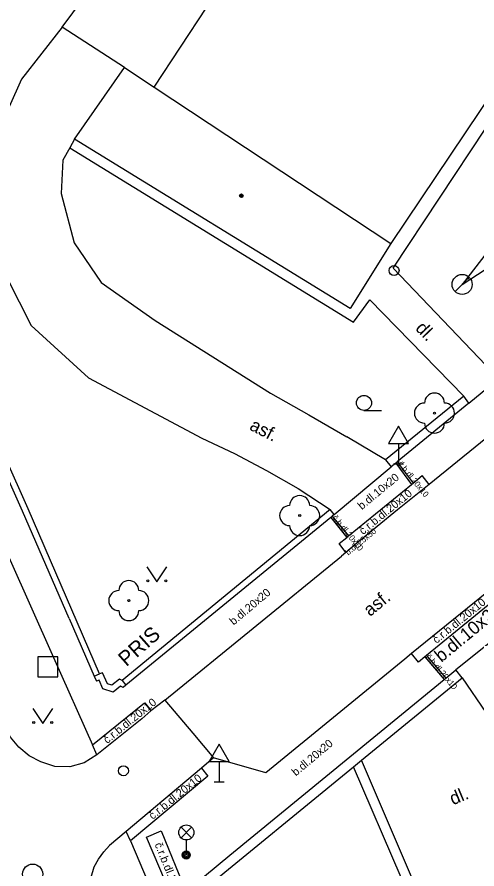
# Model space of a CAD drawing. Extents: x -600391 to -599491, y -1160176 to -1159402.
# Drawn here: x -599970.71 to -599947.75, y -1159959.22 to -1159916.65 of the extents above; entities that cross this region are included whole.
import ezdxf

# ---------------------------------------------------------------- set-up
doc = ezdxf.new("R2010")
doc.units = 0
for name, color, linetype in [('Level 10', 7, 'Continuous'), ('Level 11', 7, 'Continuous'), ('Level 14', 7, 'Continuous'), ('Level 15', 7, 'Continuous'), ('Level 22', 7, 'Continuous'), ('Level 26', 7, 'Continuous'), ('Level 27', 7, 'Continuous'), ('Level 28', 7, 'Continuous'), ('Level 31', 7, 'Continuous'), ('Level 33', 7, 'Continuous'), ('Level 34', 7, 'Continuous'), ('Level 36', 7, 'Continuous'), ('Level 39', 7, 'Continuous'), ('Level 40', 7, 'Continuous'), ('Level 41', 7, 'Continuous'), ('Level 5', 7, 'Continuous'), ('Level 7', 7, 'Continuous'), ('Level 8', 7, 'Continuous')]:
    doc.layers.add(name, color=color, linetype=linetype)

msp = doc.modelspace()

# ---------------------------------------------------------------- linework, layer by layer
at = {"layer": 'Level 10'}
for points in [[(-599911.82, -1159908.6), (-599914.96, -1159911.33), (-599925.54, -1159919.92), (-599941.57, -1159933.04), (-599950.13, -1159940)], [(-599907.98, -1159913.43), (-599912.46, -1159917.06), (-599914.77, -1159918.94), (-599915.47, -1159919.52), (-599917.71, -1159921.29), (-599918.18, -1159921.69), (-599922.35, -1159925.05), (-599925.54, -1159927.69), (-599925.9, -1159927.97), (-599936.86, -1159936.91), (-599937.36, -1159937.36), (-599940.49, -1159939.85), (-599940.86, -1159940.15), (-599941.25, -1159940.48), (-599946.99, -1159945.18), (-599947.87, -1159945.9)], [(-599950.13, -1159940), (-599951.71, -1159941.28), (-599953.75, -1159942.94)], [(-599953.75, -1159942.94), (-599954.29, -1159943.4), (-599954.52, -1159943.59)], [(-599963.33, -1159950.78), (-599954.52, -1159943.59)], [(-599947.87, -1159945.9), (-599951.01, -1159948.46)], [(-599951.35, -1159948.74), (-599958.29, -1159954.41)], [(-599951.01, -1159948.46), (-599951.35, -1159948.74)], [(-599963.33, -1159950.78), (-599964.03, -1159951.32), (-599964.48, -1159951.71)], [(-599964.48, -1159951.71), (-599966.73, -1159953.52)], [(-599969.53, -1159953.86), (-599970.11, -1159953.56), (-599970.62, -1159953.14), (-599971.04, -1159952.63), (-599971.35, -1159952.05)], [(-599966.73, -1159953.52), (-599967.36, -1159953.92), (-599968.08, -1159954.11), (-599968.82, -1159954.09), (-599969.53, -1159953.86)], [(-599958.29, -1159954.41), (-599960.91, -1159953.67), (-599961.5, -1159954.18), (-599965.26, -1159957.34), (-599966.09, -1159958.04)], [(-599966.86, -1159959.11), (-599966.64, -1159958.73), (-599966.38, -1159958.37), (-599966.09, -1159958.04)], [(-599966.74, -1159962.81), (-599967.06, -1159961.92), (-599967.19, -1159960.97), (-599967.13, -1159960.02), (-599966.86, -1159959.11)]]:
    msp.add_lwpolyline(points, dxfattribs=at)
at = {"layer": 'Level 11'}
for points in [[(-600002.37, -1159877.7), (-599997.64, -1159887.06), (-599995.54, -1159891.34), (-599992.33, -1159897.82), (-599988.83, -1159905.02), (-599982.55, -1159918.34), (-599977.69, -1159928.9), (-599968.89, -1159948.65)], [(-599965.34, -1159919.17), (-599968.46, -1159917.15), (-599964.35, -1159911.61), (-599976.85, -1159896), (-599973.76, -1159893.33)], [(-599951.94, -1159929.2), (-599940.37, -1159911.69)], [(-599968.46, -1159917.15), (-599970.48, -1159919.75), (-599971.67, -1159922.37), (-599972.15, -1159925.31), (-599971.83, -1159928.48), (-599970, -1159932.06), (-599967.15, -1159934.67), (-599961.48, -1159937.69)], [(-599967.84, -1159922.75), (-599968.08, -1159923.18), (-599968.42, -1159923.8), (-599968.5, -1159925.47), (-599967.86, -1159927.93), (-599966.51, -1159929.91), (-599963.81, -1159931.82), (-599958.06, -1159935.45)], [(-599968.08, -1159923.18), (-599953.91, -1159931.89)], [(-599951.94, -1159929.2), (-599946.95, -1159934.41)], [(-599953.91, -1159931.89), (-599953.1, -1159930.78)], [(-599953.1, -1159930.78), (-599948.41, -1159935.6)], [(-599958.06, -1159935.45), (-599956.14, -1159936.53), (-599954.24, -1159937.62)], [(-599961.48, -1159937.69), (-599959.85, -1159938.46), (-599958.25, -1159939.3), (-599956.68, -1159940.2), (-599955.08, -1159941.26)], [(-599952.31, -1159938.78), (-599954.24, -1159937.62)], [(-599951.8, -1159938.94), (-599951.02, -1159940)], [(-599951.73, -1159938.88), (-599950.94, -1159939.94)], [(-599954.29, -1159943.4), (-599954.63, -1159942.96), (-599954.25, -1159942.65), (-599954.17, -1159942.58), (-599951.02, -1159940), (-599950.94, -1159939.94), (-599950.49, -1159939.56)], [(-599950.13, -1159940), (-599950.49, -1159939.56)], [(-599955.05, -1159941.66), (-599954.25, -1159942.65)], [(-599954.97, -1159941.59), (-599954.17, -1159942.58)], [(-599946.99, -1159945.18), (-599946.66, -1159945.62), (-599947.11, -1159945.98), (-599947.19, -1159946.04), (-599950.27, -1159948.55), (-599950.35, -1159948.61), (-599950.67, -1159948.88), (-599951.01, -1159948.46)], [(-599968.89, -1159948.65), (-599966.94, -1159953.01)], [(-599950.35, -1159948.61), (-599949.38, -1159949.75)], [(-599950.27, -1159948.55), (-599949.3, -1159949.68)], [(-599948.48, -1159949.66), (-599943.76, -1159956.6)], [(-599966.94, -1159953.01), (-599964.35, -1159950.91), (-599964.03, -1159951.32)], [(-599963.33, -1159950.78), (-599961.94, -1159952.43), (-599960.91, -1159953.67)], [(-599966.73, -1159953.52), (-599966.94, -1159953.01)], [(-599950.96, -1159959.73), (-599953.51, -1159953.78)], [(-599961.5, -1159954.18), (-599961.19, -1159954.58), (-599965.04, -1159957.82)], [(-599951.53, -1159959.65), (-599953.91, -1159954.11)], [(-599962.27, -1159960.38), (-599962.96, -1159960.65), (-599964.24, -1159957.63), (-599963.52, -1159957.31), (-599962.27, -1159960.38)], [(-599965.04, -1159957.82), (-599965.26, -1159957.34)], [(-599965.04, -1159957.82), (-599962.63, -1159963.51)]]:
    msp.add_lwpolyline(points, dxfattribs=at)
at = {"layer": 'Level 14'}
for points in [[(-599941.8, -1159921.35), (-599948.49, -1159930.01)], [(-599948.49, -1159930.01), (-599940.79, -1159924.98)]]:
    msp.add_lwpolyline(points, dxfattribs=at)
at = {"layer": 'Level 15'}
msp.add_lwpolyline([(-599948.24, -1159929.69), (-599948.18, -1159929.73)], dxfattribs=at)
at = {"layer": 'Level 22'}
for centre in [(-599949.87, -1159936.44), (-599956.6, -1159941.56), (-599965.13, -1159945.81)]:
    msp.add_circle(centre, 0.05, dxfattribs=at)
for centre, start, end in [((-599949.87, -1159935.94), 0, 180), ((-599950.37, -1159936.44), 90, 270), ((-599949.37, -1159936.44), 270, 90), ((-599949.87, -1159936.94), 180, 0), ((-599956.6, -1159941.06), 0, 180), ((-599957.1, -1159941.56), 90, 270), ((-599956.1, -1159941.56), 270, 90), ((-599956.6, -1159942.06), 180, 0), ((-599965.13, -1159945.31), 0, 180), ((-599965.63, -1159945.81), 90, 270), ((-599964.63, -1159945.81), 270, 90), ((-599965.13, -1159946.31), 180, 0)]:
    msp.add_arc(centre, 0.5, start, end, dxfattribs=at)
at = {"layer": 'Level 26'}
msp.add_lwpolyline([(-599969.67, -1159949.62), (-599968.67, -1159949.62), (-599968.67, -1159948.62), (-599969.67, -1159948.62)], close=True, dxfattribs=at)
at = {"layer": 'Level 27'}
msp.add_line((-599948.844, -1159930.363), (-599948.137, -1159929.656), dxfattribs=at)
for centre in [(-599948.49, -1159930.01), (-599969.93, -1159959.47)]:
    msp.add_circle(centre, 0.5, dxfattribs=at)
at = {"layer": 'Level 28'}
msp.add_circle((-599951.89, -1159929.32), 0.25, dxfattribs=at)
at = {"layer": 'Level 31'}
msp.add_circle((-599965.4, -1159954.31), 0.25, dxfattribs=at)
at = {"layer": 'Level 33'}
for p, q in [((-599962.525, -1159957.66), (-599961.995, -1159957.13)), ((-599962.525, -1159957.13), (-599961.995, -1159957.66)), ((-599962.26, -1159957.77), (-599962.26, -1159958.52))]:
    msp.add_line(p, q, dxfattribs=at)
for centre, radius in [((-599962.26, -1159957.395), 0.375), ((-599962.26, -1159958.52), 0.2), ((-599962.26, -1159958.52), 0.145), ((-599962.26, -1159958.52), 0.0876)]:
    msp.add_circle(centre, radius, dxfattribs=at)
at = {"layer": 'Level 34'}
for p, q in [((-599951.66, -1159937.952), (-599951.66, -1159938.97)), ((-599951.91, -1159938.97), (-599951.41, -1159938.97)), ((-599960.62, -1159953.842), (-599960.62, -1159954.86)), ((-599960.87, -1159954.86), (-599960.37, -1159954.86))]:
    msp.add_line(p, q, dxfattribs=at)
for points in [[(-599952.16, -1159937.952), (-599951.16, -1159937.952), (-599951.66, -1159937.086)], [(-599961.12, -1159953.842), (-599960.12, -1159953.842), (-599960.62, -1159952.976)]]:
    msp.add_lwpolyline(points, close=True, dxfattribs=at)
at = {"layer": 'Level 36'}
msp.add_line((-599953.39, -1159936.305), (-599952.515, -1159936.305), dxfattribs=at)
for points in [[(-599964.23, -1159944.12), (-599963.73, -1159944.87), (-599963.23, -1159944.12)], [(-599969.93, -1159951.2), (-599969.43, -1159951.95), (-599968.93, -1159951.2)]]:
    msp.add_lwpolyline(points, dxfattribs=at)
for centre, radius in [((-599953.39, -1159935.93), 0.375), ((-599964.18, -1159944.82), 0.05), ((-599963.281, -1159944.82), 0.05), ((-599969.88, -1159951.9), 0.05), ((-599968.981, -1159951.9), 0.05)]:
    msp.add_circle(centre, radius, dxfattribs=at)
at = {"layer": 'Level 39'}
for radius in [0.09, 0.0398]:
    msp.add_circle((-599959.51, -1159925.58), radius, dxfattribs=at)
at = {"layer": 'Level 5'}
for points in [[(-599940.17, -1159910.25), (-599952.05, -1159927.96)], [(-599963.86, -1159920.16), (-599961.23, -1159916.15)], [(-599967.84, -1159922.75), (-599965.34, -1159919.17)], [(-599965.34, -1159919.17), (-599963.86, -1159920.16)], [(-599963.86, -1159920.16), (-599952.05, -1159927.96)], [(-599954.08, -1159931.21), (-599967.84, -1159922.75)], [(-599952.05, -1159927.96), (-599954.08, -1159931.21)]]:
    msp.add_lwpolyline(points, dxfattribs=at)
at = {"layer": 'Level 7'}
for points in [[(-599968.11, -1159946.7), (-599970.43, -1159941.34), (-599977.26, -1159926)], [(-599970.16, -1159941.22), (-599976.99, -1159925.88)], [(-599948.41, -1159935.6), (-599952.31, -1159938.78)], [(-599948.15, -1159935.94), (-599948.41, -1159935.6)], [(-599948.15, -1159935.94), (-599951.73, -1159938.88), (-599951.8, -1159938.94), (-599952.03, -1159939.13)], [(-599952.31, -1159938.78), (-599952.03, -1159939.13)], [(-599966.59, -1159949.46), (-599970.16, -1159941.22)], [(-599955.08, -1159941.26), (-599965.47, -1159949.8)], [(-599954.87, -1159941.51), (-599954.97, -1159941.59), (-599955.05, -1159941.66), (-599965.28, -1159950.03)], [(-599954.87, -1159941.51), (-599955.08, -1159941.26)], [(-599968.11, -1159946.7), (-599966.86, -1159949.58)], [(-599966.86, -1159949.58), (-599966.59, -1159949.46)], [(-599966.86, -1159949.58), (-599966.75, -1159949.84)], [(-599966.45, -1159949.42), (-599966.59, -1159949.46)], [(-599966.2, -1159949.97), (-599966.45, -1159949.42)], [(-599959.16, -1159966.49), (-599961.71, -1159960.51), (-599953.91, -1159954.11), (-599953.51, -1159953.78), (-599948.48, -1159949.66)], [(-599950.5, -1159950.66), (-599949.38, -1159949.75), (-599949.3, -1159949.68), (-599948.8, -1159949.27)], [(-599948.48, -1159949.66), (-599948.8, -1159949.27)], [(-599966.61, -1159949.79), (-599966.75, -1159949.84)], [(-599966.42, -1159950.21), (-599966.61, -1159949.79)], [(-599965.97, -1159950.04), (-599966.2, -1159949.97)], [(-599965.59, -1159949.74), (-599965.97, -1159950.04)], [(-599965.55, -1159950.09), (-599965.91, -1159950.38)], [(-599965.47, -1159949.8), (-599965.59, -1159949.74)], [(-599965.28, -1159950.03), (-599965.42, -1159950.15), (-599965.55, -1159950.09)], [(-599965.47, -1159949.8), (-599965.28, -1159950.03)], [(-599965.91, -1159950.38), (-599966.42, -1159950.21)], [(-599962.27, -1159960.38), (-599961.36, -1159959.57), (-599960.09, -1159958.52), (-599950.5, -1159950.66)]]:
    msp.add_lwpolyline(points, dxfattribs=at)
at = {"layer": 'Level 8'}
for points in [[(-599948.15, -1159935.94), (-599946.82, -1159934.84)], [(-599954.87, -1159941.51), (-599952.03, -1159939.13)], [(-599946.82, -1159947.68), (-599948.8, -1159949.27)]]:
    msp.add_lwpolyline(points, dxfattribs=at)

# ---------------------------------------------------------------- texts
at = {"layer": 'Level 40'}
for s, height, rotation, p in [('dl.', 0.65, 313.9358, (-599950.86, -1159932.24)), ('asf.', 0.65, 332.9527, (-599959.15, -1159937.25)), ('č.b.dl.20x10', 0.3, 309, (-599951.72, -1159938.99)), ('b.dl.10x20', 0.4, 39.5617, (-599953.5, -1159941.29)), ('č.r.b.dl.20x10', 0.39999, 39, (-599953.44, -1159942.54)), ('č.b.dl.20x10', 0.3, 309, (-599954.99, -1159941.68)), ('b.dl.25x50', 0.3, 39.0428, (-599954.18, -1159943.56)), ('b.dl.20x20', 0.4, 40.1478, (-599959.9, -1159947.06)), ('asf.', 0.65, 39.2848, (-599953.09, -1159946.63)), ('č.r.b.dl.20x10', 0.39999, 39, (-599949.77, -1159947.98)), ('b.dl.10x20', 0.65, 39.5617, (-599949.53, -1159948.92)), ('č.b.dl.20x10', 0.3, 310, (-599950.32, -1159948.63)), ('č.r.b.dl.20x10', 0.39999, 39, (-599966.21, -1159952.98)), ('b.dl.20x20', 0.4, 40.1478, (-599956.79, -1159954.6)), ('č.r.b.dl.20x10', 0.39999, 39, (-599963.94, -1159956.77)), ('dl.', 0.65, 22.6614, (-599948.95, -1159956.04)), ('č.r.b.dl.20x10', 0.39999, 292, (-599963.85, -1159957.99))]:
    msp.add_text(s, height=height, rotation=rotation, dxfattribs=at).set_placement(p)
at = {"layer": 'Level 41'}
msp.add_text('PRIS', height=0.75, rotation=41.4385, dxfattribs=at).set_placement((-599965.25, -1159949.14))

doc.saveas('drawing.dxf')
